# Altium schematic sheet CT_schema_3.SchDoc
size 187 x 169 mm
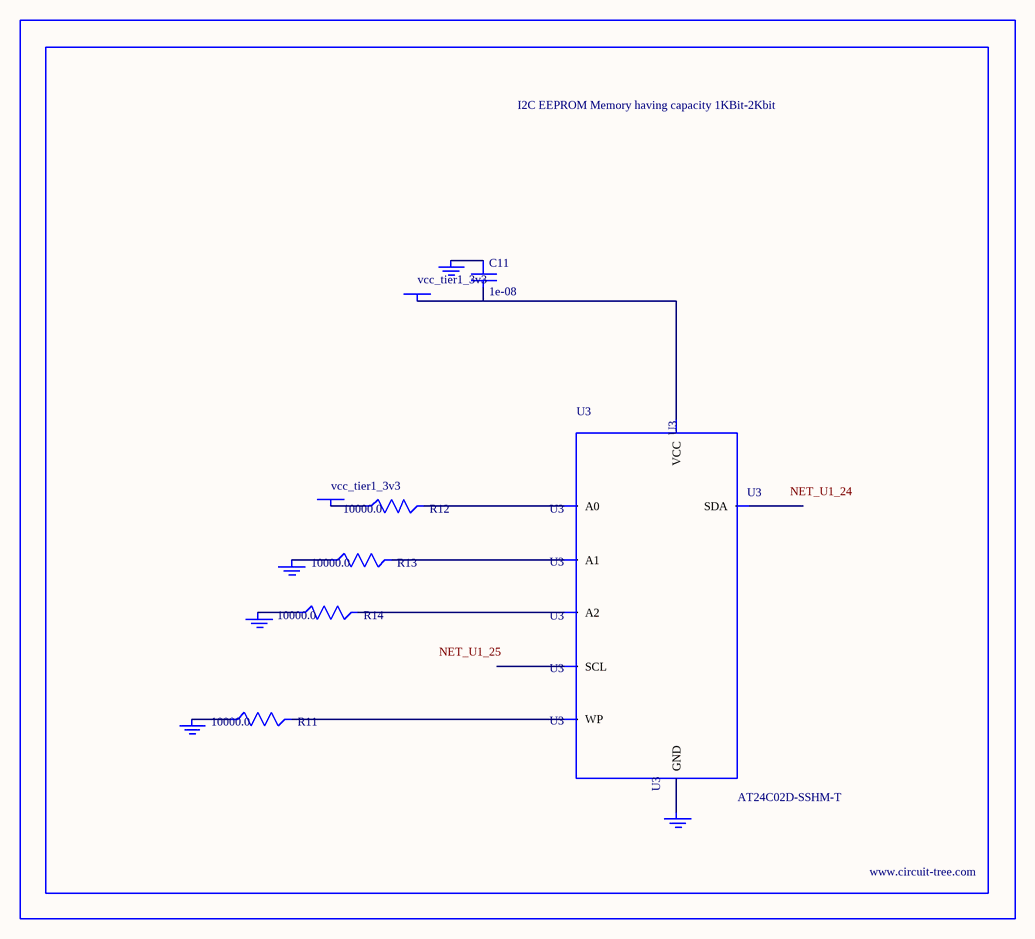
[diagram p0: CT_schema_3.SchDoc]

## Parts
BORDER2  (no value)
C11  1e-08  [C0402]
GND_INSTANCE_2_0  (no value)
GND_INSTANCE_2_1  (no value)
GND_INSTANCE_2_2  (no value)
GND_INSTANCE_2_3  (no value)
GND_INSTANCE_2_4  (no value)
POWER_INSTANCE_2_0  vcc_tier1_3v3
POWER_INSTANCE_2_1  vcc_tier1_3v3
R11  10000.0  [R0603]
R12  10000.0  [R0603]
R13  10000.0  [R0603]
R14  10000.0  [R0603]
U3  AT24C02D-SSHM-T  [AT24C02D]

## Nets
NetC11_1: C11.1 GND_INSTANCE_2_3.0(GND)
NetC11_2: C11.2 POWER_INSTANCE_2_1.0(PWR) U3.8(VCC)
NetGND_INSTANCE_2_0_0: GND_INSTANCE_2_0.0(GND) R13.1
NetGND_INSTANCE_2_1_0: GND_INSTANCE_2_1.0(GND) R14.1
NetGND_INSTANCE_2_2_0: GND_INSTANCE_2_2.0(GND) R11.1
NetGND_INSTANCE_2_4_0: GND_INSTANCE_2_4.0(GND) U3.4(GND)
NetPOWER_INSTANCE_2_0_0: POWER_INSTANCE_2_0.0(PWR) R12.1
NetR11_2: R11.2 U3.7(WP)
NetR12_2: R12.2 U3.1(A0)
NetR13_2: R13.2 U3.2(A1)
NetR14_2: R14.2 U3.3(A2)

Not connected (* = marked no-connect by the designer): U3 5(SDA) 6(SCL)

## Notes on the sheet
- Labels drawn without touching a wire or pin: NET_U1_24, NET_U1_25

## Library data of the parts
BORDER2 = BORDER_PAGE2
C11 = C0402C103K3RAC
GND_INSTANCE_2_0-GND_INSTANCE_2_4 = GND
POWER_INSTANCE_2_0 POWER_INSTANCE_2_1 = PWR
R11-R14 = RC0603JR-0710KL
